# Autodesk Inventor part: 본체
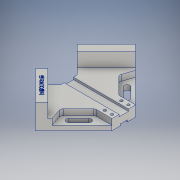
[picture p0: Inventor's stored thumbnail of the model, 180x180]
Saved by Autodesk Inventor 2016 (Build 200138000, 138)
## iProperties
Created: 2019-04
Part Number: 본체
Material: 알루미늄 6061
Document SubType Name: Modeling
Designer: 605-06
Density: 2.7 g/cm^3
Appearance: 알루미늄 - 평지
Mass: 601.509 g
Surface Area: 426.536 cm^2
Volume: 222.781 cm^3
Author: 605-06
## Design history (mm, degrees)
sketch "스케치1"
  geometry: L1 (84.853, -24.33)-(35.355, -73.827); L2 (20, 40.523)-(84.853, -24.33); L3 (0, -109.183)-(0, 60.523); L4 (35.355, -73.827)-(15.47, -53.941); L5 (11.934, -52.477)-(0, -52.477); L6 (20, 40.523)-(0, 40.523); A1 r 5 centre (11.934, -57.477) between (15.47, -53.941) and (11.934, -52.477); 2 further points
  constraints: 12 end point, 5 point on line, 2 perpendicular, 2 point on circle, 2 tangent, 1 centre point, 1 vertical
  dimensions: "d1" = 90 deg angle of L2 L1; "d4" = 120 distance of L1.start L3.start; "d5" = 120 distance of L3.end L1.start; "d6" = 50 distance of L1.end L3.start; "d7" = 40 diameter of L2.start L3; "d8" = 45 deg angle of L3 L1; "d9" = 93 distance between parallel lines of L5 L6; "d10" = 90 deg angle of L4 L1; "d49" = 5 radius of A1; "d57" = 20 distance from line of L3.end L6
extrude "돌출1" new body sketch "스케치1" distance "d11" = 18; taper "d12" = 0 deg
sketch "스케치2"
  geometry: L1 (-15.47, 53.941)-(-35.355, 73.827) reference; L2 (-84.853, 24.33)-(-20, -40.523) reference; L3 (-74.246, 13.723)-(-24.749, 63.221); L4 (-84.853, 24.33)-(-35.355, 73.827) reference; 2 further points
  constraints: 2 end point, 2 point on line, 1 perpendicular
  dimensions: "d14" = 15 distance between parallel lines of L4 L3
extrude "돌출2" join sketch "스케치2" distance "d15" = 24; taper "d16" = 0 deg
sketch "스케치3"
  geometry: L1 (-74.246, 13.723)-(-20, -40.523) reference; L2 (-70.711, 10.188)-(-52.429, 16.281); L3 (-47.312, 15.074)-(-21.464, -10.774); L4 (-20, -14.31)-(-20, -40.523); L5 (-35.355, 73.827)-(-84.853, 24.33) reference; L6 (-49.497, 3.117)-(-32.527, -13.854); L7 (-49.497, 3.117)-(-32.527, -13.854); L8 (-52.679, -0.065)-(-35.709, -17.036); L9 (-29.345, -10.672)-(-46.315, 6.299); A1 r 4.5 centre (-49.497, 3.117) between (-46.315, 6.299) and (-52.679, -0.065); A2 r 4.5 centre (-32.527, -13.854) between (-35.709, -17.036) and (-29.345, -10.672); A3 r 5 centre (-50.848, 11.538) between (-47.312, 15.074) and (-52.429, 16.281); A4 r 5 centre (-25, -14.31) between (-20, -14.31) and (-21.464, -10.774); 3 further points
  constraints: 16 end point, 8 point on circle, 8 tangent, 4 centre point, 3 parallel, 3 point on line, 1 collinear, 1 midpoint, 1 vertical
  dimensions: "d17" = 20 distance between parallel lines of L3 L1; "d18" = 20 distance from line of L2.start L5; "d19" = 30 distance from line of point (-49.497, 17.259) L5; "d20" = 9 diameter of A2; "d21" = 24 distance of L6.start L6.end; "d22" = 40 distance from line of L5 L6.start; "d23" = 10 distance between parallel lines of L6 L1; "d24" = 5 radius of A3; "d25" = 5 radius of A4
extrude "돌출3" cut sketch "스케치3" distance "d26" = 10; taper "d27" = 0 deg
extrude "돌출4" cut sketch "스케치3" stored distance "d28" = 10; taper "d29" = 0 deg
sketch "스케치5"
  geometry: L1 (0, -52.477)-(0, 40.523) reference; L2 (0, 40.523)-(-20, 40.523) reference; 3 further points
  constraints: 1 vertical alignment
  dimensions: "d33" = 14 distance from line of L1 point (-14, 34.523); "d34" = 6 distance from line of L2 point (-14, 34.523); "d35" = 12 distance of point (-14, 34.523) point (-14, 22.523)
hole "구멍1" sketch "스케치5" at (-14, 34.523), (-14, 22.523) diameter "d36" = 4.5; stored, may be unused: countersink angle "d40" = 90 deg, drill point angle "d42" = 118 deg; dims "d37" = 6, "d38" = 8, "d39" = 10, "d41" = 8
sketch "스케치6"
  geometry: L1 (-11.934, 52.477)-(0, 52.477) reference; L2 (-8, 52.477)-(-8, -40.523); L3 (-20, -40.523)-(0, -40.523) reference; L4 (0, -40.523)-(0, 52.477) reference; 2 further points
  constraints: 2 end point, 2 point on line, 1 vertical
  dimensions: "d43" = 8 distance between parallel lines of L4 L2
extrude "돌출5" cut sketch "스케치6" distance "d44" = 3.5; taper "d45" = 0 deg
sketch "스케치7"
  geometry: L1 (0, 40.523)-(-20, 40.523) reference; L2 (-6, 40.523)-(-6, -52.477); L3 (-8, -52.477)-(0, -52.477) reference; L4 (0, -52.477)-(0, 40.523) reference; 1 further point
  constraints: 2 end point, 2 point on line, 1 vertical
  dimensions: "d46" = 6 distance between parallel lines of L4 L2
extrude "돌출6" cut sketch "스케치7" distance "d47" = 3; taper "d48" = 0 deg
sketch "스케치8"
  geometry: L1 (-84.853, 24.33)-(-74.246, 13.723) reference; L2 (-24.749, 63.221)-(-35.355, 73.827) reference; L3 (-35.355, 73.827)-(-84.853, 24.33) reference; 2 further points
  constraints: 1 other
  dimensions: "d53" = 35 distance from line of point (-54.801, 43.775) L2; "d54" = 7.5 distance from line of L3 point (-54.801, 43.775)
feature "엠보싱1" sketch "스케치8" dims "d1" = 90 deg, "d4" = 120, "d5" = 120, "d6" = 50, "d7" = 40, "d8" = 45 deg, "d9" = 93, "d10" = 90 deg, "d49" = 5, "d55" = 0.5, "d56" = 0, "d57" = 20
node "솔리드1"
mirror "대칭3"
